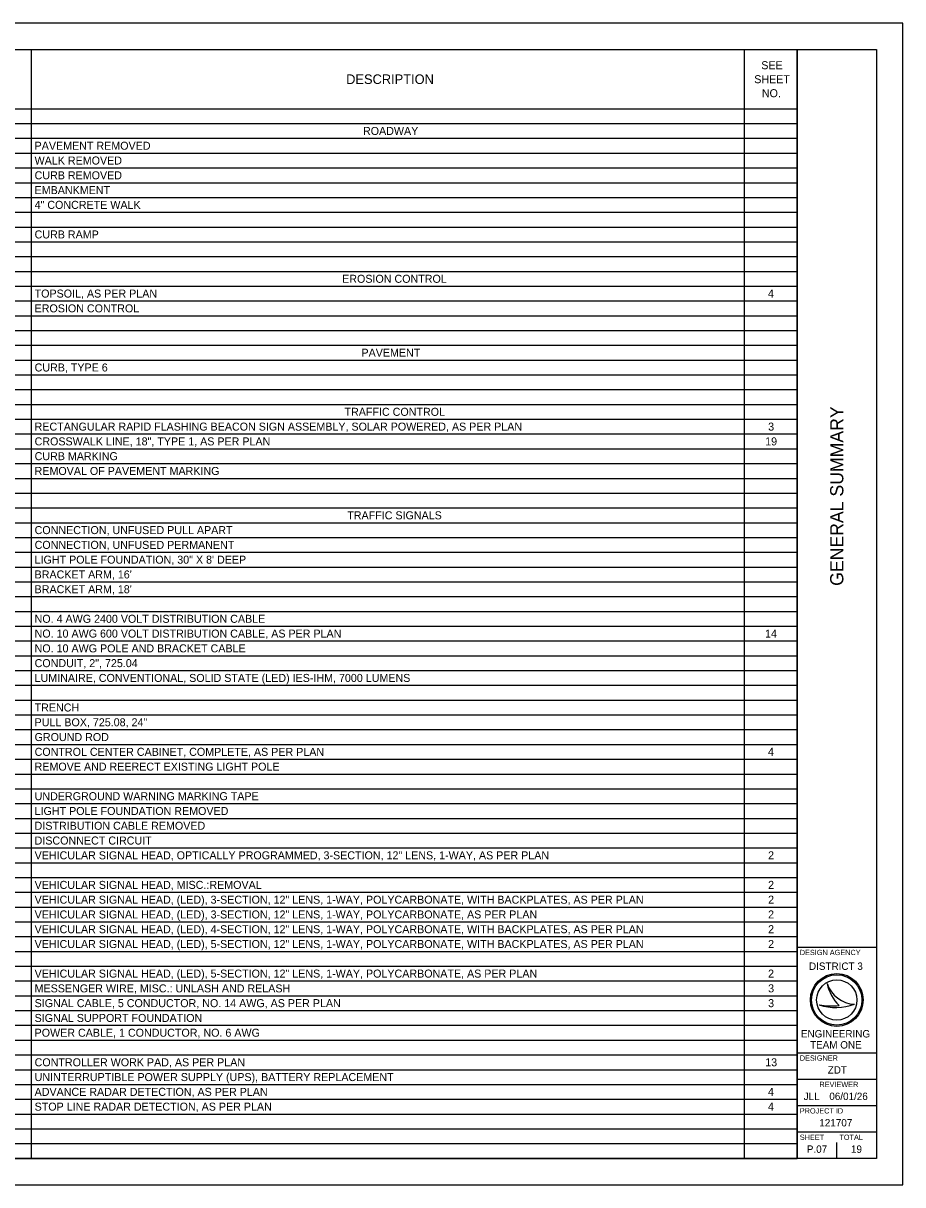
# Model space of a CAD drawing. Extents: x 0 to 34, y 0 to 22.
# Drawn here: x 17.34 to 34, y 0 to 22 of the extents above; entities that cross this region are included whole.
import ezdxf

# ---------------------------------------------------------------- set-up
doc = ezdxf.new("R2010")
doc.units = 0
for name, color, linetype in [('Default', 7, 'Continuous'), ('SH_Border', 7, 'Continuous'), ('SH_Cut_Line', 7, 'Continuous'), ('SH_Data', 7, 'Continuous')]:
    doc.layers.add(name, color=color, linetype=linetype)

msp = doc.modelspace()

# ---------------------------------------------------------------- linework, layer by layer
at = {"layer": 'Default'}
for p, q in [((1.5, 21.5), (32, 21.5)), ((17.491, 21.5), (17.491, 0.5)), ((30.995, 21.5), (30.995, 0.5)), ((32, 21.5), (32, 0.5)), ((1.5, 20.38), (32, 20.38)), ((1.5, 20.1), (32, 20.1)), ((1.5, 19.82), (32, 19.82)), ((1.5, 19.54), (32, 19.54)), ((1.5, 19.26), (32, 19.26)), ((1.5, 18.98), (32, 18.98)), ((1.5, 18.7), (32, 18.7)), ((1.5, 18.42), (32, 18.42)), ((1.5, 18.14), (32, 18.14)), ((1.5, 17.86), (32, 17.86)), ((1.5, 17.58), (32, 17.58)), ((1.5, 17.3), (32, 17.3)), ((1.5, 17.02), (32, 17.02)), ((1.5, 16.74), (32, 16.74)), ((1.5, 16.46), (32, 16.46)), ((1.5, 16.18), (32, 16.18)), ((1.5, 15.9), (32, 15.9)), ((1.5, 15.62), (32, 15.62)), ((1.5, 15.34), (32, 15.34)), ((1.5, 15.06), (32, 15.06)), ((1.5, 14.78), (32, 14.78)), ((1.5, 14.5), (32, 14.5)), ((1.5, 14.22), (32, 14.22)), ((1.5, 13.94), (32, 13.94)), ((1.5, 13.66), (32, 13.66)), ((1.5, 13.38), (32, 13.38)), ((1.5, 13.1), (32, 13.1)), ((1.5, 12.82), (32, 12.82)), ((1.5, 12.54), (32, 12.54)), ((1.5, 12.26), (32, 12.26)), ((1.5, 11.98), (32, 11.98)), ((1.5, 11.7), (32, 11.7)), ((1.5, 11.42), (32, 11.42)), ((1.5, 11.14), (32, 11.14)), ((1.5, 10.86), (32, 10.86)), ((1.5, 10.58), (32, 10.58)), ((1.5, 10.3), (32, 10.3)), ((1.5, 10.02), (32, 10.02)), ((1.5, 9.74), (32, 9.74)), ((1.5, 9.46), (32, 9.46)), ((1.5, 9.18), (32, 9.18)), ((1.5, 8.9), (32, 8.9)), ((1.5, 8.62), (32, 8.62)), ((1.5, 8.34), (32, 8.34)), ((1.5, 8.06), (32, 8.06)), ((1.5, 7.78), (32, 7.78)), ((1.5, 7.5), (32, 7.5)), ((1.5, 7.22), (32, 7.22)), ((1.5, 6.94), (32, 6.94)), ((1.5, 6.66), (32, 6.66)), ((1.5, 6.38), (32, 6.38)), ((1.5, 6.1), (32, 6.1)), ((1.5, 5.82), (32, 5.82)), ((1.5, 5.54), (32, 5.54)), ((1.5, 5.26), (32, 5.26)), ((1.5, 4.98), (32, 4.98)), ((1.5, 4.7), (32, 4.7)), ((1.5, 4.42), (32, 4.42)), ((1.5, 4.14), (32, 4.14)), ((1.5, 3.86), (32, 3.86)), ((1.5, 3.58), (32, 3.58)), ((1.5, 3.3), (32, 3.3)), ((1.5, 3.02), (32, 3.02)), ((1.5, 2.74), (32, 2.74)), ((1.5, 2.46), (32, 2.46)), ((1.5, 2.18), (32, 2.18)), ((1.5, 1.9), (32, 1.9)), ((1.5, 1.62), (32, 1.62)), ((1.5, 1.34), (32, 1.34)), ((1.5, 1.06), (32, 1.06)), ((1.5, 0.78), (32, 0.78)), ((1.5, 0.5), (32, 0.5))]:
    msp.add_line(p, q, dxfattribs=at)
at = {"layer": 'SH_Border'}
for p, q in [((32, 0.5), (32, 21.5)), ((32, 4.5), (33.5, 4.5)), ((32, 2.5), (33.5, 2.5)), ((32, 2), (33.5, 2)), ((32, 1.5), (33.5, 1.5)), ((32, 1), (33.5, 1))]:
    msp.add_line(p, q, dxfattribs=at)
msp.add_lwpolyline([(1.5, 21.5), (33.5, 21.5), (33.5, 0.5), (1.5, 0.5)], close=True, dxfattribs=at)
at = {"layer": 'SH_Cut_Line'}
msp.add_lwpolyline([(0, 0), (34, 0), (34, 22), (0, 22)], close=True, dxfattribs=at)
at = {"layer": 'SH_Data'}
for p, q in [((32.567, 3.81), (32.567, 3.81)), ((32.417, 3.41), (32.417, 3.41)), ((32.75, 3.5), (32.75, 3.5)), ((33.087, 3.419), (33.087, 3.419)), ((32.375, 0.675), (32.375, 0.675)), ((32.75, 0.5), (32.75, 0.8))]:
    msp.add_line(p, q, dxfattribs=at)
for radius in [0.5, 0.477, 0.477, 0.382]:
    msp.add_circle((32.75, 3.5), radius, dxfattribs=at)
for centre, radius, start, end in [((33.116, 3.998), 0.58, 198.9257, 198.9319), ((33.347, 3.97), 0.796, 191.6379, 191.6421), ((33.116, 3.998), 0.58, 198.9319, 267.1657), ((33.347, 3.97), 0.796, 191.6421, 226.0947), ((32.739, 4.37), 1.013, 251.4576, 290.0832), ((32.648, 4.654), 1.266, 259.4964, 259.4995), ((32.739, 4.37), 1.013, 251.4527, 251.4576), ((32.648, 4.654), 1.266, 259.4995, 276.6672)]:
    msp.add_arc(centre, radius, start, end, dxfattribs=at)

# ---------------------------------------------------------------- texts
at = {"layer": 'Default'}
for s, height, p in [('SEE ', 0.1515, (31.32, 21.129)), ('DESCRIPTION', 0.18184, (23.458, 20.849)), ('SHEET ', 0.1515, (31.187, 20.864)), ('NO.', 0.1515, (31.331, 20.599)), ('ROADWAY', 0.1515, (23.777, 19.884)), ('PAVEMENT REMOVED', 0.15153, (17.557, 19.604)), ('WALK REMOVED', 0.15153, (17.557, 19.324)), ('CURB REMOVED', 0.15153, (17.557, 19.044)), ('EMBANKMENT', 0.1515, (17.557, 18.764)), ('4" CONCRETE WALK', 0.15153, (17.557, 18.484)), ('CURB RAMP', 0.1515, (17.557, 17.924)), ('EROSION CONTROL', 0.15153, (23.382, 17.084)), ('TOPSOIL, AS PER PLAN', 0.15153, (17.557, 16.804)), ('4', 0.152, (31.446, 16.804)), ('EROSION CONTROL', 0.15153, (17.557, 16.524)), ('PAVEMENT', 0.1515, (23.748, 15.684)), ('CURB, TYPE 6', 0.15153, (17.557, 15.404)), ('TRAFFIC CONTROL', 0.15153, (23.427, 14.564)), ('RECTANGULAR RAPID FLASHING BEACON SIGN ASSEMBLY, SOLAR POWERED, AS PER PLAN', 0.15153, (17.557, 14.284)), ('3', 0.152, (31.45, 14.284)), ('CROSSWALK LINE, 18", TYPE 1, AS PER PLAN', 0.15153, (17.557, 14.004)), ('19', 0.1515, (31.394, 14.004)), ('CURB MARKING', 0.15153, (17.557, 13.724)), ('REMOVAL OF PAVEMENT MARKING', 0.15153, (17.557, 13.444)), ('TRAFFIC SIGNALS', 0.15153, (23.479, 12.604)), ('CONNECTION, UNFUSED PULL APART', 0.15153, (17.557, 12.324)), ('CONNECTION, UNFUSED PERMANENT', 0.15153, (17.557, 12.044)), ('LIGHT POLE FOUNDATION, 30" X 8\' DEEP', 0.15153, (17.557, 11.764)), ("BRACKET ARM, 16'", 0.15153, (17.557, 11.484)), ("BRACKET ARM, 18'", 0.15153, (17.557, 11.204)), ('NO. 4 AWG 2400 VOLT DISTRIBUTION CABLE', 0.15153, (17.557, 10.644)), ('NO. 10 AWG 600 VOLT DISTRIBUTION CABLE, AS PER PLAN', 0.15153, (17.557, 10.364)), ('14', 0.1515, (31.392, 10.364)), ('NO. 10 AWG POLE AND BRACKET CABLE', 0.15153, (17.557, 10.084)), ('CONDUIT, 2", 725.04', 0.15153, (17.557, 9.804)), ('LUMINAIRE, CONVENTIONAL, SOLID STATE (LED) IES-IHM, 7000 LUMENS', 0.15153, (17.557, 9.524)), ('TRENCH', 0.1515, (17.557, 8.964)), ('PULL BOX, 725.08, 24"', 0.15153, (17.557, 8.684)), ('GROUND ROD', 0.1515, (17.557, 8.404)), ('CONTROL CENTER CABINET, COMPLETE, AS PER PLAN', 0.15153, (17.557, 8.124)), ('4', 0.152, (31.446, 8.124)), ('REMOVE AND REERECT EXISTING LIGHT POLE', 0.15153, (17.557, 7.844)), ('UNDERGROUND WARNING MARKING TAPE', 0.15153, (17.557, 7.284)), ('LIGHT POLE FOUNDATION REMOVED', 0.15153, (17.557, 7.004)), ('DISTRIBUTION CABLE REMOVED', 0.15153, (17.557, 6.724)), ('DISCONNECT CIRCUIT', 0.15153, (17.557, 6.444)), ('VEHICULAR SIGNAL HEAD, OPTICALLY PROGRAMMED, 3-SECTION, 12" LENS, 1-WAY, AS PER PLAN', 0.15153, (17.557, 6.164)), ('2', 0.152, (31.449, 6.164)), ('VEHICULAR SIGNAL HEAD, MISC.:REMOVAL', 0.15153, (17.557, 5.604)), ('2', 0.152, (31.449, 5.604)), ('VEHICULAR SIGNAL HEAD, (LED), 3-SECTION, 12" LENS, 1-WAY, POLYCARBONATE, WITH BACKPLATES, AS PER PLAN', 0.151529, (17.557, 5.324)), ('2', 0.152, (31.449, 5.324)), ('VEHICULAR SIGNAL HEAD, (LED), 3-SECTION, 12" LENS, 1-WAY, POLYCARBONATE, AS PER PLAN', 0.15153, (17.557, 5.044)), ('2', 0.152, (31.449, 5.044)), ('VEHICULAR SIGNAL HEAD, (LED), 4-SECTION, 12" LENS, 1-WAY, POLYCARBONATE, WITH BACKPLATES, AS PER PLAN', 0.151529, (17.557, 4.764)), ('2', 0.152, (31.449, 4.764)), ('VEHICULAR SIGNAL HEAD, (LED), 5-SECTION, 12" LENS, 1-WAY, POLYCARBONATE, WITH BACKPLATES, AS PER PLAN', 0.151529, (17.557, 4.484)), ('2', 0.152, (31.449, 4.484)), ('VEHICULAR SIGNAL HEAD, (LED), 5-SECTION, 12" LENS, 1-WAY, POLYCARBONATE, AS PER PLAN', 0.15153, (17.557, 3.924)), ('2', 0.152, (31.449, 3.924)), ('MESSENGER WIRE, MISC.: UNLASH AND RELASH', 0.15153, (17.557, 3.644)), ('3', 0.152, (31.45, 3.644)), ('SIGNAL CABLE, 5 CONDUCTOR, NO. 14 AWG, AS PER PLAN', 0.15153, (17.557, 3.364)), ('3', 0.152, (31.45, 3.364)), ('SIGNAL SUPPORT FOUNDATION', 0.15153, (17.557, 3.084)), ('POWER CABLE, 1 CONDUCTOR, NO. 6 AWG', 0.15153, (17.557, 2.804)), ('CONTROLLER WORK PAD, AS PER PLAN', 0.15153, (17.557, 2.244)), ('13', 0.1515, (31.395, 2.244)), ('UNINTERRUPTIBLE POWER SUPPLY (UPS), BATTERY REPLACEMENT', 0.15153, (17.557, 1.964)), ('ADVANCE RADAR DETECTION, AS PER PLAN', 0.15153, (17.557, 1.684)), ('4', 0.152, (31.446, 1.684)), ('STOP LINE RADAR DETECTION, AS PER PLAN', 0.15153, (17.557, 1.404)), ('4', 0.152, (31.446, 1.404))]:
    msp.add_text(s, height=height, dxfattribs=at).set_placement(p)
at = {"layer": 'SH_Data'}
msp.add_text('GENERAL SUMMARY', height=0.25, rotation=90, dxfattribs=at).set_placement((32.875, 11.344))
for s, height, p in [('DESIGN AGENCY', 0.1, (32.05, 4.35)), ('DISTRICT 3', 0.14, (32.224, 4.07)), ('ENGINEERING', 0.14, (32.071, 2.79)), ('TEAM ONE', 0.14, (32.244, 2.58)), ('DESIGNER', 0.1, (32.05, 2.35)), ('ZDT', 0.14, (32.579, 2.105)), ('REVIEWER', 0.1, (32.422, 1.85)), ('JLL', 0.14, (32.123, 1.605)), ('06/01/26', 0.14, (32.609, 1.605)), ('PROJECT ID', 0.1, (32.05, 1.35)), ('121707', 0.14, (32.42, 1.105)), ('SHEET', 0.1, (32.05, 0.85)), ('TOTAL', 0.1, (32.8, 0.85)), ('P.07', 0.14, (32.183, 0.605)), ('19', 0.14, (33.019, 0.605))]:
    msp.add_text(s, height=height, dxfattribs=at).set_placement(p)

doc.saveas('drawing.dxf')
